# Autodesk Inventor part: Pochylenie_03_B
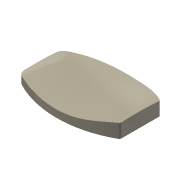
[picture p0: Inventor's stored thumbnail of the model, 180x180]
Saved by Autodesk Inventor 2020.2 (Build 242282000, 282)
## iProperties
Created: 2005-05
Part Number: Pochylenie_03_B
Document SubType Name: Modeling
Designer: F.Stasiak
Manufacturer: Standard
Standards Organization: Custom
Stock Number: Ćwiczenie_5_54b
Density: 1 g/cm^3
Material: Ogólny
Appearance: Jasnobeżowa
Manager: www.cadconsulting.pl
Company: Fabian Stasiak CAD Consulting
Author: F.Stasiak
Subject: Zbiór ćwiczeń. Autodesk Inventor 2020. Kurs podstawowy
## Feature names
1. Wyciągnięcie proste1 [Extrusion]
2. Zaokrąglenie1 [Fillet]
3. Podział5
## Parameters: d4 = 0, d5 = 0, d10 = 15 mm, d11 = 5 mm, d12 = 0, d15 = 0, d16 = 0
